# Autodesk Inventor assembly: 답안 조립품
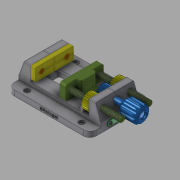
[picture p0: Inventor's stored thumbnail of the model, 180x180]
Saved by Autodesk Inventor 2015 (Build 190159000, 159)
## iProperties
Created: 2018-03
Part Number: 답안 조립품
Document SubType Name: Assembly
Designer: SCD-A03
Author: SCD-A03
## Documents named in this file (10)
- C:\Users\SCD-A03\Desktop\380308V1003\답안 조립품.iam
- C:\Users\SCD-A03\Desktop\380308V1003\바이스본체 A.ipt
- C:\Users\SCD-A03\Desktop\380308V1003\고정 플레이트.ipt
- C:\Users\SCD-A03\Desktop\380308V1003\바이스본체 B.ipt
- C:\Users\SCD-A03\Desktop\380308V1003\스퍼기어.ipt
- C:\Users\SCD-A03\Desktop\380308V1003\슬라이딩 부품.ipt
- C:\Users\SCD-A03\Desktop\380308V1003\십자오목머리나사 M3.ipt
- C:\Users\SCD-A03\Desktop\380308V1003\십자오목머리나사 M4.ipt
- C:\Users\SCD-A03\Desktop\380308V1003\지지대.ipt
- C:\Users\SCD-A03\Desktop\380308V1003\핸들.ipt
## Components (3 placed, 2 different names)
1. 고정 플레이트:1
2. 핸들:1 — 구동부
3. 고정 플레이트:2
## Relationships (1: Angle 1)
- 구동부 [Angle]: 핸들:1
